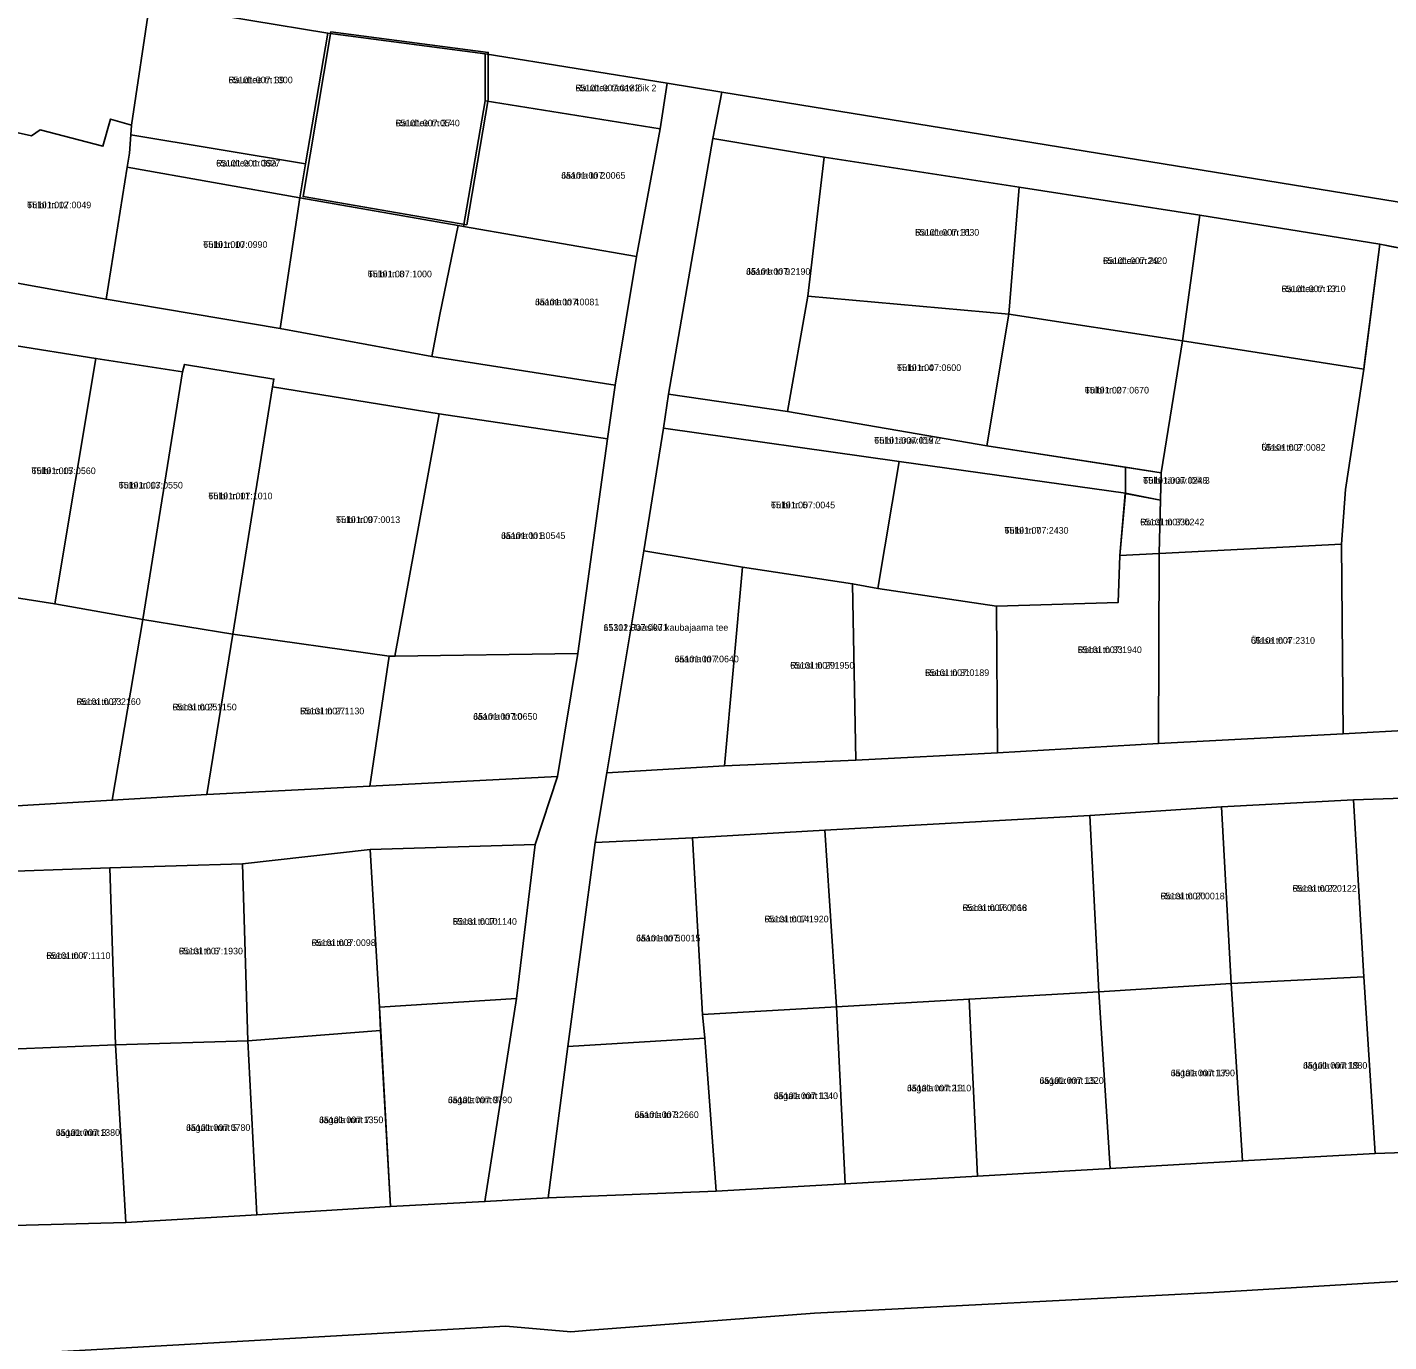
# Model space of a CAD drawing. Extents: x 556044 to 574504, y 6567077 to 6586269.
# Drawn here: x 566608.6 to 566916.3, y 6581099.3 to 6581396.3 of the extents above; entities that cross this region are included whole.
import ezdxf

# ---------------------------------------------------------------- set-up
doc = ezdxf.new("R2010")
doc.units = 0
for name, color, linetype in [('L_AADRESS', 7, 'Continuous'), ('PIIR', 7, 'Continuous'), ('TUNNUS', 7, 'Continuous')]:
    doc.layers.add(name, color=color, linetype=linetype)

msp = doc.modelspace()

# ---------------------------------------------------------------- linework, layer by layer
at = {"layer": 'PIIR'}
for points in [[(566545.01, 6581418.8), (566596.01, 6581409.19), (566636.31, 6581401.93), (566632.17, 6581374.24), (566627.41, 6581375.58), (566625.68, 6581369.45), (566611.47, 6581373.15), (566609.52, 6581371.81), (566590.56, 6581376.03), (566538.63, 6581386.36)], [(566636.31, 6581401.93), (566641.71, 6581400.74), (566676.5, 6581395.01), (566671.48, 6581365.45), (566632, 6581372), (566632.17, 6581374.24)], [(566707.91, 6581351.69), (566670.91, 6581358.09), (566677.21, 6581395.31), (566712.77, 6581390.67), (566712.75, 6581380.01)], [(566712.08, 6581390.36), (566753.21, 6581383.71), (566751.62, 6581373.41), (566712.06, 6581379.69)], [(566765.59, 6581381.67), (566763.54, 6581371.21), (566753.49, 6581313.4), (566752.42, 6581305.72), (566747.96, 6581278.04), (566739.59, 6581227.9), (566736.96, 6581212.11), (566730.75, 6581166.03), (566726.34, 6581131.82), (566712.04, 6581130.98), (566719.19, 6581176.89), (566723.39, 6581211.68), (566728.44, 6581227.06), (566733.05, 6581254.82), (566739.73, 6581303.35), (566741.5, 6581315.47), (566746.26, 6581344.55), (566751.62, 6581373.41), (566753.21, 6581383.71)], [(567188.26, 6581313.03), (567223.2, 6581307.36), (567271.87, 6581299.83), (567272.87, 6581307.59), (567306.72, 6581302.39), (567306.4, 6581283.39), (567270.42, 6581288.84), (567227.5, 6581296.43), (567206.67, 6581300.57), (567184.98, 6581303.9), (567184.69, 6581302.1), (567141.1, 6581307.33), (567107.66, 6581313.53), (567011.2, 6581331.44), (566976.83, 6581337.17), (566930.83, 6581344.13), (566914.3, 6581347.3), (566873.58, 6581353.89), (566832.77, 6581360.19), (566788.67, 6581366.96), (566763.54, 6581371.21), (566765.59, 6581381.67)], [(566707.21, 6581351.35), (566712.06, 6581379.69), (566751.62, 6581373.41), (566746.26, 6581344.55)], [(566609.52, 6581371.81), (566611.47, 6581373.15), (566625.68, 6581369.45), (566627.41, 6581375.58), (566632.17, 6581374.24), (566632, 6581372), (566631.68, 6581367.89), (566631.16, 6581364.76), (566626.39, 6581334.87), (566585.4, 6581342.27), (566590.56, 6581376.03)], [(566671.48, 6581365.45), (566670.18, 6581357.77), (566631.16, 6581364.76), (566631.68, 6581367.89), (566632, 6581372)], [(566780.42, 6581309.54), (566753.49, 6581313.4), (566763.54, 6581371.21), (566788.67, 6581366.96), (566785.04, 6581335.56)], [(566785.04, 6581335.56), (566788.67, 6581366.96), (566832.77, 6581360.19), (566830.43, 6581331.54)], [(566626.39, 6581334.87), (566631.16, 6581364.76), (566670.18, 6581357.77), (566665.78, 6581328.24)], [(566873.58, 6581353.89), (566869.73, 6581325.48), (566830.43, 6581331.54), (566832.77, 6581360.19)], [(566700.06, 6581321.93), (566665.78, 6581328.24), (566670.18, 6581357.77), (566705.96, 6581351.57), (566701.86, 6581331.46)], [(566873.58, 6581353.89), (566914.3, 6581347.3), (566910.67, 6581319.09), (566869.73, 6581325.48)], [(566705.96, 6581351.57), (566707.21, 6581351.35), (566746.26, 6581344.55), (566741.5, 6581315.47), (566700.06, 6581321.93), (566701.86, 6581331.46)], [(566921.91, 6581289.95), (566922.39, 6581237.62), (566906.05, 6581236.7), (566905.65, 6581279.52), (566906.51, 6581291.9), (566910.67, 6581319.09), (566910.85, 6581320.48), (566914.3, 6581347.3), (566917.22, 6581346.74), (566930.83, 6581344.13), (566926.92, 6581318.43), (566924, 6581301.85)], [(566780.42, 6581309.54), (566785.04, 6581335.56), (566830.43, 6581331.54), (566825.5, 6581301.79)], [(566830.43, 6581331.54), (566869.73, 6581325.48), (566864.87, 6581295.65), (566825.5, 6581301.79)], [(566869.73, 6581325.48), (566910.67, 6581319.09), (566906.51, 6581291.9), (566905.65, 6581279.52), (566864.41, 6581277.43), (566864.87, 6581295.65)], [(566604.3, 6581324.68), (566624.11, 6581321.52), (566614.81, 6581266.06), (566604.74, 6581267.67), (566595, 6581269.22)], [(566624.11, 6581321.52), (566643.68, 6581318.5), (566634.7, 6581262.54), (566614.81, 6581266.06)], [(566664.32, 6581316.85), (566664.03, 6581315.06), (566655.02, 6581259.21), (566634.7, 6581262.54), (566643.68, 6581318.5), (566644.09, 6581320.16)], [(566701.71, 6581308.98), (566691.68, 6581254.2), (566690.38, 6581254.22), (566655.02, 6581259.21), (566664.03, 6581315.06)], [(566753.49, 6581313.4), (566780.42, 6581309.54), (566825.5, 6581301.79), (566856.81, 6581296.91), (566856.79, 6581291.08), (566805.64, 6581298.24), (566752.42, 6581305.72)], [(566691.68, 6581254.2), (566701.71, 6581308.98), (566739.73, 6581303.35), (566733.05, 6581254.82)], [(566805.64, 6581298.24), (566800.8, 6581269.56), (566795.14, 6581270.59), (566770.22, 6581274.32), (566747.96, 6581278.04), (566752.42, 6581305.72)], [(566855.57, 6581276.96), (566855.19, 6581266.39), (566827.62, 6581265.56), (566800.8, 6581269.56), (566805.64, 6581298.24), (566856.79, 6581291.08)], [(566856.81, 6581296.91), (566864.87, 6581295.65), (566864.76, 6581289.47), (566856.79, 6581291.08)], [(566856.76, 6581291.01), (566864.76, 6581289.47), (566864.41, 6581277.43), (566855.51, 6581276.98)], [(566906.05, 6581236.7), (566864.24, 6581234.49), (566864.41, 6581277.43), (566905.65, 6581279.52)], [(566766.21, 6581229.49), (566739.59, 6581227.9), (566747.96, 6581278.04), (566770.22, 6581274.32)], [(566827.85, 6581232.42), (566827.62, 6581265.56), (566855.19, 6581266.39), (566855.57, 6581276.96), (566864.41, 6581277.43), (566864.24, 6581234.49)], [(566766.21, 6581229.49), (566770.22, 6581274.32), (566795.14, 6581270.59), (566795.83, 6581230.73)], [(566795.14, 6581270.59), (566800.8, 6581269.56), (566827.62, 6581265.56), (566827.85, 6581232.42), (566795.83, 6581230.73)], [(566604.74, 6581267.67), (566614.81, 6581266.06), (566634.7, 6581262.54), (566627.81, 6581221.69), (566604.91, 6581220.38)], [(566468.87, 6581263.93), (566475.06, 6581260.4), (566507.78, 6581238.03), (566526.58, 6581226.82), (566525.95, 6581223.01), (566546.72, 6581222.22), (566546.79, 6581222.66), (566580.77, 6581218.83), (566604.91, 6581220.38), (566627.81, 6581221.69), (566649.15, 6581222.99), (566685.98, 6581224.89), (566728.44, 6581227.06), (566723.39, 6581211.68), (566686.12, 6581210.55), (566657.24, 6581207.33), (566627.26, 6581206.38), (566597.25, 6581205.37), (566567.44, 6581204.07), (566567.33, 6581206.34), (566524.94, 6581211.72), (566489.74, 6581232.59), (566464.41, 6581250.57)], [(566634.7, 6581262.54), (566655.02, 6581259.21), (566649.15, 6581222.99), (566627.81, 6581221.69)], [(566655.02, 6581259.21), (566690.38, 6581254.22), (566685.98, 6581224.89), (566649.15, 6581222.99)], [(566728.44, 6581227.06), (566685.98, 6581224.89), (566690.38, 6581254.22), (566691.68, 6581254.2), (566733.05, 6581254.82)], [(566878.49, 6581220.22), (566908.34, 6581221.77), (566910.66, 6581181.8), (566880.7, 6581180.25)], [(566908.34, 6581221.77), (566923.99, 6581222.27), (566926.31, 6581182.29), (566928.63, 6581142.36), (566913.24, 6581141.88), (566910.66, 6581181.8)], [(566791.5, 6581175.01), (566788.87, 6581214.9), (566848.76, 6581218.27), (566850.82, 6581178.4), (566821.45, 6581176.76)], [(566880.7, 6581180.25), (566850.82, 6581178.4), (566848.76, 6581218.27), (566878.49, 6581220.22)], [(566761.2, 6581173.26), (566758.92, 6581213.19), (566788.87, 6581214.9), (566791.5, 6581175.01)], [(566686.12, 6581210.55), (566723.39, 6581211.68), (566719.19, 6581176.89), (566688.18, 6581174.92)], [(566736.96, 6581212.11), (566758.92, 6581213.19), (566761.2, 6581173.26), (566761.71, 6581167.94), (566730.75, 6581166.03)], [(566657.24, 6581207.33), (566686.12, 6581210.55), (566688.18, 6581174.92), (566688.43, 6581169.62), (566658.41, 6581167.35)], [(566627.26, 6581206.38), (566628.53, 6581166.4), (566599.21, 6581165.2), (566597.25, 6581205.37)], [(566627.26, 6581206.38), (566657.24, 6581207.33), (566658.41, 6581167.35), (566628.53, 6581166.4)], [(566910.66, 6581181.8), (566913.24, 6581141.88), (566883.28, 6581140.17), (566880.7, 6581180.25)], [(566850.82, 6581178.4), (566853.33, 6581138.46), (566823.38, 6581136.75), (566821.45, 6581176.76)], [(566880.7, 6581180.25), (566883.28, 6581140.17), (566853.33, 6581138.46), (566850.82, 6581178.4)], [(566688.18, 6581174.92), (566719.19, 6581176.89), (566712.04, 6581130.98), (566690.71, 6581129.89)], [(566761.2, 6581173.26), (566791.5, 6581175.01), (566793.43, 6581135.03), (566764.29, 6581133.36), (566761.71, 6581167.94)], [(566821.45, 6581176.76), (566823.38, 6581136.75), (566793.43, 6581135.03), (566791.5, 6581175.01)], [(566658.41, 6581167.35), (566688.43, 6581169.62), (566690.71, 6581129.89), (566660.47, 6581127.98)], [(566599.21, 6581165.2), (566628.53, 6581166.4), (566630.86, 6581126.24), (566599.81, 6581125.47)], [(566628.53, 6581166.4), (566658.41, 6581167.35), (566660.47, 6581127.98), (566630.86, 6581126.24)], [(566726.34, 6581131.82), (566730.75, 6581166.03), (566761.71, 6581167.94), (566764.29, 6581133.36)]]:
    msp.add_lwpolyline(points, close=True, dxfattribs=at)
for points in [[(567492.22, 6581273.86), (567306.72, 6581302.39), (567272.87, 6581307.59), (567276.04, 6581332.24), (567227.66, 6581339.69), (567193.1, 6581344.94), (567188.26, 6581313.03), (566765.59, 6581381.67), (566753.21, 6581383.71), (566712.08, 6581390.36), (566676.5, 6581395.01), (566641.71, 6581400.74), (566636.31, 6581401.93), (566596.01, 6581409.19)], [(566585.4, 6581342.27), (566626.39, 6581334.87), (566665.78, 6581328.24), (566700.06, 6581321.93), (566741.5, 6581315.47), (566739.73, 6581303.35), (566701.71, 6581308.98), (566664.03, 6581315.06), (566664.32, 6581316.85), (566644.09, 6581320.16), (566643.68, 6581318.5), (566624.11, 6581321.52), (566604.3, 6581324.68)], [(566923.99, 6581222.27), (566908.34, 6581221.77), (566878.49, 6581220.22), (566848.76, 6581218.27), (566788.87, 6581214.9), (566758.92, 6581213.19), (566736.96, 6581212.11), (566739.59, 6581227.9), (566766.21, 6581229.49), (566795.83, 6581230.73), (566827.85, 6581232.42), (566864.24, 6581234.49), (566906.05, 6581236.7), (566922.39, 6581237.62)], [(567375.89, 6581174.08), (567310.28, 6581150.81), (567247.63, 6581135.95), (567235.82, 6581134.12), (567199.69, 6581128.67), (567018.1, 6581118.96), (566876.68, 6581110.46), (566786.5, 6581105.8), (566735.82, 6581101.91), (566731.48, 6581101.58), (566716.72, 6581102.84), (566490.87, 6581089.97)], [(566599.81, 6581125.47), (566630.86, 6581126.24), (566660.47, 6581127.98), (566690.71, 6581129.89), (566712.04, 6581130.98), (566726.34, 6581131.82), (566764.29, 6581133.36), (566793.43, 6581135.03), (566823.38, 6581136.75), (566853.33, 6581138.46), (566883.28, 6581140.17), (566913.24, 6581141.88), (566928.63, 6581142.36)]]:
    msp.add_lwpolyline(points, dxfattribs=at)

# ---------------------------------------------------------------- texts
at = {"layer": 'L_AADRESS'}
for s, p in [('Raudtee tn 39', (566654.08, 6581383.69)), ('Raudtee tänav lõik 2', (566732.5, 6581381.88)), ('Raudtee tn 37', (566691.84, 6581373.94)), ('Raudtee tn 39a', (566651.28, 6581364.88)), ('Jaama tn 2', (566729.29, 6581362.12)), ('Tulbi tn 12', (566608.54, 6581355.45)), ('Raudtee tn 31', (566809.25, 6581349.25)), ('Tulbi tn 10', (566648.37, 6581346.5)), ('Raudtee tn 29', (566851.72, 6581342.84)), ('Tulbi tn 8', (566685.54, 6581339.85)), ('Jaama tn 9', (566771.08, 6581340.41)), ('Raudtee tn 27', (566892.07, 6581336.49)), ('Jaama tn 4', (566723.37, 6581333.52)), ('Tulbi tn 4', (566805.17, 6581318.67)), ('Tulbi tn 2', (566847.62, 6581313.59)), ('Tulbi tänav lõik 2', (566800.03, 6581302.24)), ('Ülase tn 2', (566887.54, 6581300.65)), ('Tulbi tn 15', (566609.55, 6581295.37)), ('Tulbi tänav lõik 3', (566860.81, 6581293.19)), ('Tulbi tn 13', (566629.25, 6581292.12)), ('Tulbi tn 11', (566649.51, 6581289.69)), ('Tulbi tn 5', (566776.68, 6581287.64)), ('Tulbi tn 9', (566678.37, 6581284.33)), ('Roosi tn 33b', (566860.13, 6581283.79)), ('Jaama tn 8', (566715.7, 6581280.73)), ('Tulbi tn 7', (566829.44, 6581281.9)), ('11312 Raasiku kaubajaama tee', (566738.82, 6581259.97)), ('Ülase tn 4', (566885.14, 6581257.04)), ('Roosi tn 33', (566846.01, 6581254.93)), ('Jaama tn 7', (566754.91, 6581252.85)), ('Roosi tn 29', (566781.02, 6581251.41)), ('Roosi tn 31', (566811.5, 6581249.76)), ('Roosi tn 23', (566619.72, 6581243.21)), ('Roosi tn 25', (566641.42, 6581241.98)), ('Roosi tn 27', (566670.25, 6581241.1)), ('Jaama tn 10', (566709.39, 6581239.86)), ('Roosi tn 22', (566894.57, 6581201.01)), ('Roosi tn 20', (566864.73, 6581199.29)), ('Roosi tn 16 // 18', (566819.98, 6581196.64)), ('Roosi tn 10', (566704.75, 6581193.54)), ('Roosi tn 14', (566775.21, 6581194.09)), ('Roosi tn 8', (566672.84, 6581188.75)), ('Jaama tn 5', (566746.23, 6581189.78)), ('Roosi tn 4', (566612.89, 6581185.83)), ('Roosi tn 6', (566642.83, 6581186.86)), ('Jägala mnt 19', (566896.97, 6581161.02)), ('Jägala mnt 15', (566837.39, 6581157.6)), ('Jägala mnt 17', (566867.05, 6581159.32)), ('Jägala mnt 13', (566807.44, 6581155.89)), ('Jägala mnt 9', (566703.68, 6581153.23)), ('Jägala mnt 11', (566777.32, 6581154.15)), ('Jägala mnt 7', (566674.56, 6581148.72)), ('Jaama tn 3', (566745.86, 6581149.88)), ('Jägala mnt 3', (566615.04, 6581145.85)), ('Jägala mnt 5', (566644.5, 6581146.97))]:
    msp.add_text(s, height=1.5, dxfattribs=at).set_placement(p)
at = {"layer": 'TUNNUS'}
for s, p in [('65101:007:1300', (566654.08, 6581383.69)), ('65101:007:0182', (566732.5, 6581381.88)), ('65101:007:0540', (566691.84, 6581373.94)), ('65101:001:0627', (566651.28, 6581364.88)), ('65101:007:0065', (566729.29, 6581362.12)), ('65101:007:0049', (566608.54, 6581355.45)), ('65101:007:1630', (566809.25, 6581349.25)), ('65101:007:0990', (566648.37, 6581346.5)), ('65101:007:2420', (566851.72, 6581342.84)), ('65101:007:1000', (566685.54, 6581339.85)), ('65101:007:2190', (566771.08, 6581340.41)), ('65101:007:1310', (566892.07, 6581336.49)), ('65101:007:0081', (566723.37, 6581333.52)), ('65101:007:0600', (566805.17, 6581318.67)), ('65101:007:0670', (566847.62, 6581313.59)), ('65101:007:0197', (566800.03, 6581302.24)), ('65101:007:0082', (566887.54, 6581300.65)), ('65101:007:0560', (566609.55, 6581295.37)), ('65101:007:0248', (566860.81, 6581293.19)), ('65101:007:0550', (566629.25, 6581292.12)), ('65101:007:1010', (566649.51, 6581289.69)), ('65101:007:0045', (566776.68, 6581287.64)), ('65101:007:0013', (566678.37, 6581284.33)), ('65101:007:0242', (566860.13, 6581283.79)), ('65101:001:0545', (566715.7, 6581280.73)), ('65101:007:2430', (566829.44, 6581281.9)), ('65101:007:0071', (566738.82, 6581259.97)), ('65101:007:2310', (566885.14, 6581257.04)), ('65101:007:1940', (566846.01, 6581254.93)), ('65101:007:0640', (566754.91, 6581252.85)), ('65101:007:1950', (566781.02, 6581251.41)), ('65101:007:0189', (566811.5, 6581249.76)), ('65101:007:2160', (566619.72, 6581243.21)), ('65101:007:1150', (566641.42, 6581241.98)), ('65101:007:1130', (566670.25, 6581241.1)), ('65101:007:0650', (566709.39, 6581239.86)), ('65101:007:0122', (566894.57, 6581201.01)), ('65101:007:0018', (566864.73, 6581199.29)), ('65101:007:0066', (566819.98, 6581196.64)), ('65101:007:1140', (566704.75, 6581193.54)), ('65101:007:1920', (566775.21, 6581194.09)), ('65101:007:0098', (566672.84, 6581188.75)), ('65101:007:0015', (566746.23, 6581189.78)), ('65101:007:1110', (566612.89, 6581185.83)), ('65101:007:1930', (566642.83, 6581186.86)), ('65101:007:1880', (566896.97, 6581161.02)), ('65101:007:1320', (566837.39, 6581157.6)), ('65101:007:1390', (566867.05, 6581159.32)), ('65101:007:2110', (566807.44, 6581155.89)), ('65101:007:0790', (566703.68, 6581153.23)), ('65101:007:1340', (566777.32, 6581154.15)), ('65101:007:1350', (566674.56, 6581148.72)), ('65101:007:2660', (566745.86, 6581149.88)), ('65101:007:1380', (566615.04, 6581145.85)), ('65101:007:0780', (566644.5, 6581146.97))]:
    msp.add_text(s, height=1.5, dxfattribs=at).set_placement(p)

doc.saveas('drawing.dxf')
